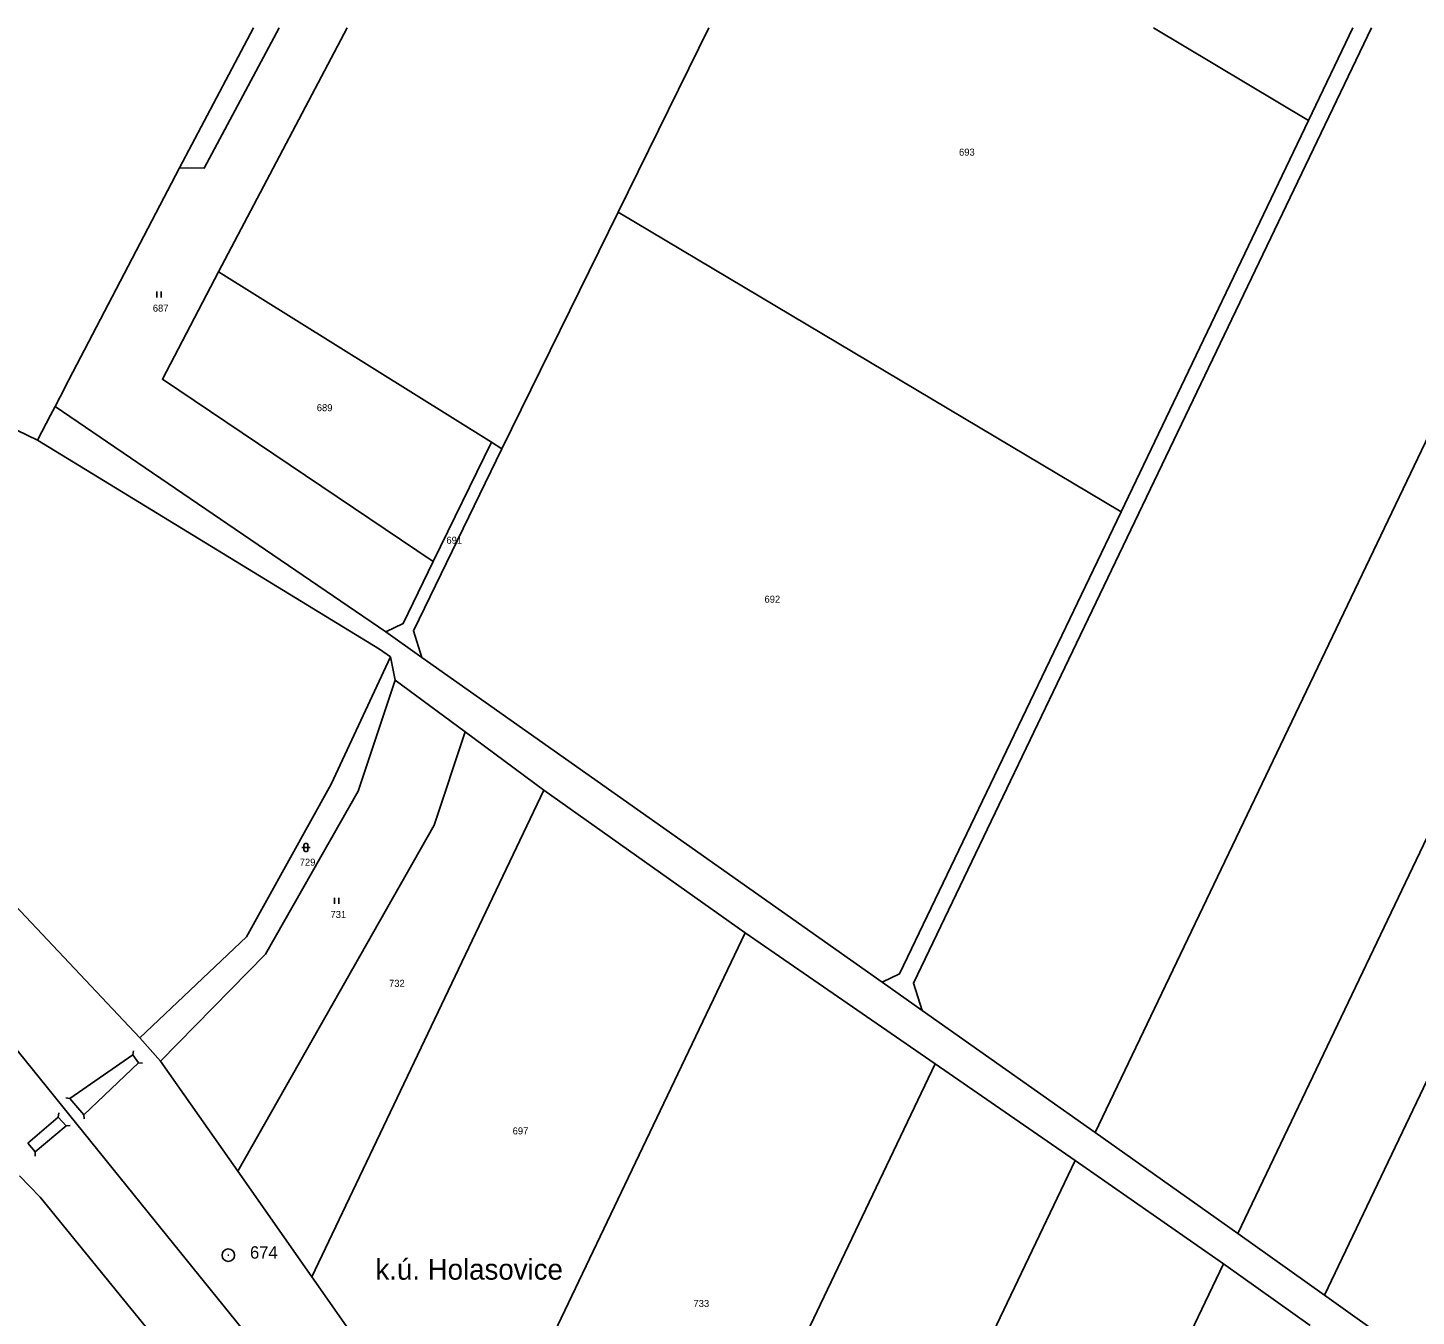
# Model space of a CAD drawing. Extents: x -504997 to -503568, y -1079870 to -1078007.
# Drawn here: x -504219.1 to -503883.2, y -1079186.7 to -1078875 of the extents above; entities that cross this region are included whole.
import ezdxf

# ---------------------------------------------------------------- set-up
doc = ezdxf.new("R2010")
doc.units = 0
for name, color, linetype in [('Hranice parcel', 7, 'Continuous'), ('Parcelní čísla', 7, 'Continuous'), ('Polygon ku', 7, 'Continuous'), ('Vnitřní kresba', 7, 'Continuous'), ('Vrstva 30', 7, 'Continuous'), ('Vrstva 31', 7, 'Continuous'), ('Vrstva 32', 7, 'Continuous'), ('Vrstva 54', 7, 'Continuous'), ('Značky kultur', 7, 'Continuous')]:
    doc.layers.add(name, color=color, linetype=linetype)

msp = doc.modelspace()

# ---------------------------------------------------------------- linework, layer by layer
at = {"layer": 'Hranice parcel'}
for p, q in [((-504182.41, -1078908.88), (-504164.51, -1078875.01)), ((-504076.26, -1078919.59), (-504054.37, -1078875.01)), ((-503946.76, -1078875.01), (-503909.28, -1078897.41)), ((-503909.28, -1078897.41), (-503898.55, -1078875.01)), ((-503954.64, -1078992.12), (-503909.28, -1078897.41)), ((-504104.41, -1078976.91), (-504076.26, -1078919.59)), ((-503954.64, -1078992.12), (-504076.26, -1078919.59)), ((-504172.99, -1078934.08), (-504106.96, -1078975.25)), ((-504248.02, -1078959.95), (-504216.74, -1078974.75)), ((-504213.62, -1078968.77), (-504212.53, -1078966.67)), ((-504212.53, -1078966.67), (-504211.31, -1078964.34)), ((-504132.52, -1079021.15), (-504212.53, -1078966.67)), ((-504216.74, -1078974.75), (-504213.62, -1078968.77)), ((-504121.02, -1079004.17), (-504106.96, -1078975.25)), ((-504106.96, -1078975.25), (-504104.41, -1078976.91)), ((-504123.75, -1079027.4), (-504132.52, -1079021.15)), ((-504131.37, -1079027.17), (-504130.21, -1079032.82)), ((-504123.75, -1079027.4), (-504012.46, -1079105.9)), ((-504130.21, -1079032.82), (-504113.31, -1079045.35)), ((-504094.24, -1079059.5), (-504113.31, -1079045.35)), ((-504150.39, -1079177.22), (-504094.24, -1079059.5)), ((-504094.24, -1079059.5), (-504045.55, -1079093.99)), ((-504045.55, -1079093.99), (-504109.47, -1079227.67)), ((-503999.6, -1079125.68), (-504045.55, -1079093.99)), ((-504012.46, -1079105.9), (-504002.73, -1079112.77)), ((-504002.73, -1079112.77), (-503960.91, -1079142.29)), ((-504187.04, -1079125.02), (-504191.97, -1079119.35)), ((-504168.33, -1079151.66), (-504187.04, -1079125.02)), ((-504070.38, -1079273.8), (-503999.6, -1079125.68)), ((-503965.74, -1079149.03), (-503999.6, -1079125.68)), ((-503960.91, -1079142.29), (-503926.36, -1079166.74)), ((-503965.74, -1079149.03), (-504041.43, -1079307.47)), ((-503929.86, -1079174.07), (-503965.74, -1079149.03)), ((-504150.39, -1079177.22), (-504168.33, -1079151.66)), ((-503926.36, -1079166.74), (-503905.42, -1079181.64)), ((-503929.86, -1079174.07), (-504008.27, -1079338.19)), ((-503908.92, -1079188.96), (-503929.86, -1079174.07)), ((-503905.42, -1079181.64), (-503850.5, -1079220.7))]:
    msp.add_line(p, q, dxfattribs=at)
for points in [[(-504158.31, -1078875.01), (-504176.41, -1078908.95), (-504182.41, -1078908.88)], [(-504141.85, -1078875.01), (-504172.99, -1078934.08)], [(-503894.08, -1078875.01), (-503926.89, -1078943.47), (-504004.86, -1079106.18), (-504002.73, -1079112.77)], [(-503832.99, -1078875.01), (-503883.7, -1078980.97), (-503960.91, -1079142.29)], [(-503787.07, -1078875.01), (-503845.26, -1078996.89), (-503926.36, -1079166.74)], [(-503758.93, -1078875.01), (-503827.49, -1079018.52), (-503905.42, -1079181.64)], [(-504211.31, -1078964.34), (-504209.15, -1078960.2), (-504182.41, -1078908.88)], [(-504172.99, -1078934.08), (-504186.53, -1078960.06), (-504121.02, -1079004.17)], [(-504191.97, -1079119.35), (-504259.1, -1079048.24), (-504304.84, -1078993.19), (-504309, -1078988.18), (-504326.93, -1078966.59)], [(-504216.74, -1078974.75), (-504134.02, -1079025.32), (-504131.37, -1079027.17)], [(-504048.32, -1079336.41), (-504164.13, -1079193.65), (-504189.98, -1079161.66), (-504303.4, -1079021.3), (-504338.19, -1078978.95)], [(-504104.41, -1078976.91), (-504125.84, -1079020.94), (-504123.75, -1079027.4)], [(-504012.46, -1079105.9), (-504008.21, -1079103.89), (-503954.64, -1078992.12)], [(-504121.02, -1079004.17), (-504128.3, -1079019.16), (-504132.52, -1079021.15)], [(-504131.37, -1079027.17), (-504145.76, -1079058.04), (-504166.2, -1079094.95), (-504191.97, -1079119.35)], [(-504130.21, -1079032.82), (-504139.18, -1079059.71), (-504161.6, -1079099.12), (-504187.04, -1079125.02)], [(-504113.31, -1079045.35), (-504120.83, -1079067.9), (-504168.33, -1079151.66)], [(-504221.12, -1079152.74), (-504216.11, -1079157.97), (-504183.22, -1079198.33)], [(-504109.47, -1079227.67), (-504141.49, -1079189.89), (-504150.39, -1079177.22)]]:
    msp.add_lwpolyline(points, dxfattribs=at)
at = {"layer": 'Vnitřní kresba'}
for p, q in [((-504208.92, -1079134.03), (-504193.73, -1079123.52)), ((-504193.56, -1079122.53), (-504193.73, -1079123.52)), ((-504193.73, -1079123.52), (-504192.37, -1079125.45)), ((-504205.52, -1079137.98), (-504192.37, -1079125.45)), ((-504191.37, -1079125.5), (-504192.37, -1079125.45)), ((-504209.91, -1079133.91), (-504208.92, -1079134.03)), ((-504208.92, -1079134.03), (-504205.52, -1079137.98)), ((-504211.57, -1079137.57), (-504211.76, -1079138.55)), ((-504205.5, -1079138.98), (-504205.52, -1079137.98)), ((-504219.12, -1079144.85), (-504211.76, -1079138.55)), ((-504217.33, -1079146.99), (-504209.84, -1079140.69)), ((-504209.84, -1079140.69), (-504211.76, -1079138.55)), ((-504208.84, -1079140.6), (-504209.84, -1079140.69)), ((-504217.33, -1079146.99), (-504219.12, -1079144.85)), ((-504217.33, -1079147.99), (-504217.33, -1079146.99))]:
    msp.add_line(p, q, dxfattribs=at)
at = {"layer": 'Vrstva 30'}
msp.add_line((-504170.7, -1079171.99), (-504170.5, -1079171.99), dxfattribs=at)
msp.add_circle((-504170.6, -1079171.99), 1.51, dxfattribs=at)
at = {"layer": 'Vrstva 31'}
msp.add_line((-504170.6, -1079171.99), (-504170.6, -1079171.99), dxfattribs=at)
at = {"layer": 'Vrstva 54'}
for points in [[(-503895.86, -1079458.07), (-503942.64, -1079419.51), (-503946.4, -1079416.88), (-503945.84, -1079414.89), (-503977.25, -1079388.9), (-504014.44, -1079358.14), (-504038.99, -1079330.47), (-504044.97, -1079331.7), (-504048.32, -1079336.41), (-504164.13, -1079193.65), (-504189.98, -1079161.66), (-504303.4, -1079021.3)], [(-504259.1, -1079048.24), (-504191.97, -1079119.35), (-504187.04, -1079125.02), (-504168.33, -1079151.66), (-504150.39, -1079177.22), (-504141.49, -1079189.89), (-504109.47, -1079227.67), (-504070.38, -1079273.8), (-504043.38, -1079305.66), (-504041.43, -1079307.47), (-504008.27, -1079338.19), (-503988.82, -1079356.2), (-503938.33, -1079402.97), (-503888.76, -1079443.21)]]:
    msp.add_lwpolyline(points, dxfattribs=at)
at = {"layer": 'Značky kultur'}
for p, q in [((-504187.88, -1078940.29), (-504187.88, -1078938.79)), ((-504186.88, -1078940.29), (-504186.88, -1078938.79)), ((-504152.83, -1079073.34), (-504150.83, -1079073.34)), ((-504152.33, -1079072.84), (-504152.33, -1079073.84)), ((-504151.33, -1079073.84), (-504151.33, -1079072.84)), ((-504144.89, -1079086.99), (-504144.89, -1079085.49)), ((-504143.89, -1079086.99), (-504143.89, -1079085.49))]:
    msp.add_line(p, q, dxfattribs=at)
for centre, start, end in [((-504151.83, -1079072.84), 0, 180), ((-504151.83, -1079073.84), 180, 359.9879)]:
    msp.add_arc(centre, 0.5, start, end, dxfattribs=at)

# ---------------------------------------------------------------- texts
at = {"layer": 'Parcelní čísla'}
for s, p in [('693', (-503993.83, -1078905.95)), ('687', (-504188.87, -1078943.69)), ('689', (-504149.2, -1078967.78)), ('691', (-504117.84, -1078999.85)), ('692', (-504040.89, -1079014.12)), ('729', (-504153.33, -1079077.74)), ('731', (-504145.88, -1079090.39)), ('732', (-504131.72, -1079107.05)), ('697', (-504101.82, -1079142.76)), ('733', (-504058.07, -1079184.51))]:
    msp.add_text(s, height=1.7, dxfattribs=at).set_placement(p)
at = {"layer": 'Polygon ku'}
msp.add_text('k.ú. Holasovice', height=5, dxfattribs=at).set_placement((-504135.01, -1079177.9))
at = {"layer": 'Vrstva 32'}
msp.add_text('674', height=3, dxfattribs=at).set_placement((-504165.36, -1079172.82))

doc.saveas('drawing.dxf')
